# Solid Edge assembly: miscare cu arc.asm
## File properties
Author: user
Template: Normal.asm
Last saved by: Lambrescu
Revision: 5
Application: Solid Edge
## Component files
cadru.par
culisa.par
tija.par
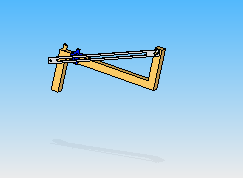
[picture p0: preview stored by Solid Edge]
